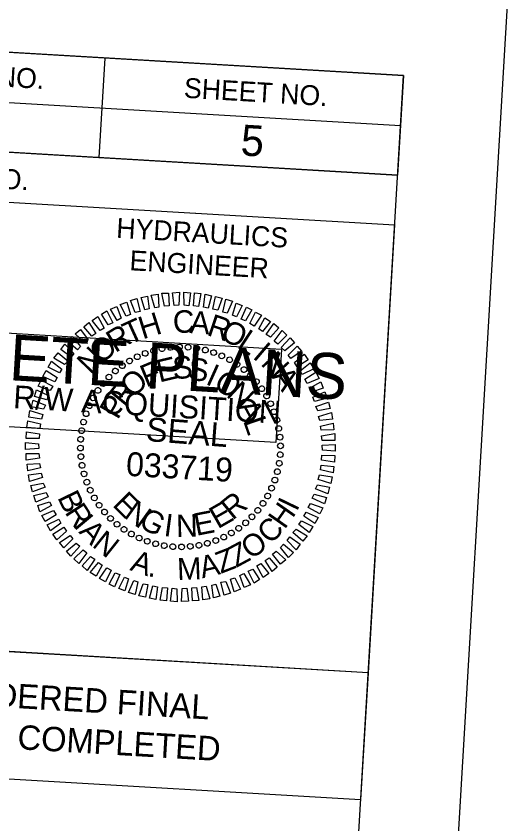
# Model space of a CAD drawing. Extents: x 2012250 to 2014096, y 444445 to 445643.
# Drawn here: x 2013972.6 to 2014096.1, y 445331.9 to 445534.5 of the extents above; entities that cross this region are included whole.
import ezdxf

# ---------------------------------------------------------------- set-up
doc = ezdxf.new("R2010")
doc.units = 0
for name, color, linetype in [('Old_Level_45', 7, 'Continuous'), ('Sheet Data Text CELL', 7, 'Continuous'), ('Sheet Plot Border Outside CELL', 7, 'Continuous'), ('Sheet Professional Seal CELL', 7, 'Continuous'), ('Sheet Profile Grid Minor CELL', 7, 'Continuous'), ('Sheet Sticker Exception Certification CELL', 7, 'Continuous'), ('Sheet Sticker Incomplete CELL', 7, 'Continuous')]:
    doc.layers.add(name, color=color, linetype=linetype)

msp = doc.modelspace()

# ---------------------------------------------------------------- linework, layer by layer
at = {"layer": 'Old_Level_45'}
for p, q in [((2013994.8, 445523.97), (2013993.33, 445499.01)), ((2013869.23, 445518.85), (2014068.93, 445507.08)), ((2013868.5, 445506.37), (2014068.2, 445494.6))]:
    msp.add_line(p, q, dxfattribs=at)
for points in [[(2014069.67, 445519.6), (2012572.27, 445607.87), (2012510.48, 444559.69), (2014007.88, 444471.42)], [(2013869.97, 445531.38), (2014069.67, 445519.6), (2014068.2, 445494.6), (2013868.5, 445506.37)], [(2013967.64, 445488), (2014067.46, 445482.12), (2014060.84, 445369.81), (2013961.02, 445375.7)]]:
    msp.add_lwpolyline(points, close=True, dxfattribs=at)
at = {"layer": 'Sheet Plot Border Outside CELL'}
msp.add_lwpolyline([(2012334.32, 444545.03), (2014031.37, 444445), (2014096.1, 445543.09), (2012399.05, 445643.13)], close=True, dxfattribs=at)
at = {"layer": 'Sheet Professional Seal CELL'}
for p, q in [((2014004.96, 445449.95), (2014004.96, 445449.95)), ((2014007.01, 445450.63), (2014007.01, 445450.63)), ((2014009.14, 445451.1), (2014009.14, 445451.1)), ((2014011.36, 445451.37), (2014011.36, 445451.37)), ((2014013.52, 445451.55), (2014013.52, 445451.55)), ((2014015.72, 445451.47), (2014015.72, 445451.47)), ((2014017.91, 445451.19), (2014017.91, 445451.19)), ((2014020.03, 445450.71), (2014020.03, 445450.71)), ((2014022.1, 445450.14), (2014022.1, 445450.14)), ((2014000.99, 445448.03), (2014000.99, 445448.03)), ((2014002.96, 445449.06), (2014002.96, 445449.06)), ((2014024.16, 445449.32), (2014024.16, 445449.32)), ((2014026.1, 445448.3), (2014026.1, 445448.3)), ((2013999.17, 445446.88), (2013999.17, 445446.88)), ((2014027.99, 445447.19), (2014027.99, 445447.19)), ((2014029.71, 445445.83), (2014029.71, 445445.83)), ((2013995.85, 445444.02), (2013995.85, 445444.02)), ((2013997.44, 445445.48), (2013997.44, 445445.48)), ((2014031.38, 445444.38), (2014031.38, 445444.38)), ((2013994.4, 445442.35), (2013994.4, 445442.35)), ((2014032.84, 445442.79), (2014032.84, 445442.79)), ((2013993.04, 445440.63), (2013993.04, 445440.63)), ((2014034.24, 445441.06), (2014034.24, 445441.06)), ((2013991.93, 445438.74), (2013991.93, 445438.74)), ((2014035.39, 445439.24), (2014035.39, 445439.24)), ((2013990.91, 445436.8), (2013990.91, 445436.8)), ((2014036.42, 445437.27), (2014036.42, 445437.27)), ((2013990.09, 445434.74), (2013990.09, 445434.74)), ((2014037.3, 445435.27), (2014037.3, 445435.27)), ((2013989.52, 445432.67), (2013989.52, 445432.67)), ((2014037.99, 445433.22), (2014037.99, 445433.22)), ((2013989.04, 445430.55), (2013989.04, 445430.55)), ((2014038.46, 445431.09), (2014038.46, 445431.09)), ((2013988.76, 445428.36), (2013988.76, 445428.36)), ((2014038.73, 445428.87), (2014038.73, 445428.87)), ((2013988.68, 445426.16), (2013988.68, 445426.16)), ((2014013.79, 445426.44), (2014013.79, 445426.44)), ((2014038.9, 445426.71), (2014038.9, 445426.71)), ((2013988.86, 445424), (2013988.86, 445424)), ((2014038.82, 445424.51), (2014038.82, 445424.51)), ((2013989.13, 445421.78), (2013989.13, 445421.78)), ((2014038.55, 445422.32), (2014038.55, 445422.32)), ((2013989.6, 445419.65), (2013989.6, 445419.65)), ((2014038.07, 445420.2), (2014038.07, 445420.2)), ((2013990.28, 445417.6), (2013990.28, 445417.6)), ((2014037.5, 445418.13), (2014037.5, 445418.13)), ((2013991.17, 445415.6), (2013991.17, 445415.6)), ((2014036.67, 445416.07), (2014036.67, 445416.07)), ((2013992.2, 445413.63), (2013992.2, 445413.63)), ((2014035.66, 445414.13), (2014035.66, 445414.13)), ((2013993.35, 445411.81), (2013993.35, 445411.81)), ((2014034.55, 445412.24), (2014034.55, 445412.24)), ((2013994.75, 445410.08), (2013994.75, 445410.08)), ((2014033.19, 445410.52), (2014033.19, 445410.52)), ((2013996.21, 445408.49), (2013996.21, 445408.49)), ((2014030.15, 445407.39), (2014030.15, 445407.39)), ((2014031.74, 445408.85), (2014031.74, 445408.85)), ((2013997.88, 445407.04), (2013997.88, 445407.04)), ((2013999.6, 445405.68), (2013999.6, 445405.68)), ((2014028.42, 445405.99), (2014028.42, 445405.99)), ((2014001.49, 445404.57), (2014001.49, 445404.57)), ((2014003.43, 445403.56), (2014003.43, 445403.56)), ((2014024.63, 445403.81), (2014024.63, 445403.81)), ((2014026.6, 445404.84), (2014026.6, 445404.84)), ((2014005.49, 445402.73), (2014005.49, 445402.73)), ((2014007.56, 445402.16), (2014007.56, 445402.16)), ((2014009.68, 445401.68), (2014009.68, 445401.68)), ((2014011.87, 445401.41), (2014011.87, 445401.41)), ((2014014.07, 445401.33), (2014014.07, 445401.33)), ((2014016.23, 445401.5), (2014016.23, 445401.5)), ((2014018.45, 445401.77), (2014018.45, 445401.77)), ((2014020.58, 445402.24), (2014020.58, 445402.24)), ((2014022.63, 445402.93), (2014022.63, 445402.93))]:
    msp.add_line(p, q, dxfattribs=at)
for points in [[(2014004.9, 445460.82), (2014003.93, 445463.88), (2014005.5, 445464.24), (2014005.97, 445461.11)], [(2014007.34, 445461.33), (2014006.47, 445464.53), (2014008.19, 445464.78), (2014008.4, 445461.51)], [(2014009.76, 445461.73), (2014009.15, 445464.98), (2014010.81, 445465.03), (2014010.97, 445461.81)], [(2014012.18, 445461.89), (2014011.82, 445465.12), (2014013.53, 445465.22), (2014013.38, 445461.97)], [(2014014.69, 445461.99), (2014014.63, 445465.25), (2014016.27, 445465.11), (2014015.88, 445461.87)], [(2014017.08, 445461.8), (2014017.27, 445465.05), (2014018.92, 445464.9), (2014018.28, 445461.68)], [(2014019.57, 445461.51), (2014019.96, 445464.74), (2014021.59, 445464.34), (2014020.75, 445461.24)], [(2014021.94, 445460.97), (2014022.58, 445464.13), (2014024.21, 445463.79), (2014023.13, 445460.75)], [(2014000.15, 445459.25), (2013998.72, 445462.13), (2014000.31, 445462.74), (2014001.28, 445459.63)], [(2014002.41, 445460.16), (2014001.28, 445463.14), (2014002.82, 445463.65), (2014003.67, 445460.39)], [(2014024.45, 445460.27), (2014025.14, 445463.48), (2014026.82, 445462.98), (2014025.49, 445459.96)], [(2014026.81, 445459.48), (2014027.74, 445462.53), (2014029.26, 445461.94), (2014027.84, 445459.07)], [(2013995.66, 445457.06), (2013993.97, 445459.71), (2013995.32, 445460.58), (2013996.8, 445457.59)], [(2013997.93, 445458.17), (2013996.25, 445460.98), (2013997.84, 445461.69), (2013998.92, 445458.72)], [(2014029, 445458.45), (2014030.34, 445461.52), (2014031.7, 445460.84), (2014030.13, 445458.03)], [(2014031.19, 445457.37), (2014032.62, 445460.24), (2014034.12, 445459.45), (2014032.26, 445456.75)], [(2013993.68, 445455.67), (2013991.67, 445458.19), (2013993.08, 445459.16), (2013994.67, 445456.26)], [(2014033.42, 445456.08), (2014034.94, 445458.85), (2014036.39, 445457.91), (2014034.34, 445455.43)], [(2013989.84, 445452.59), (2013987.42, 445454.79), (2013988.73, 445455.86), (2013990.69, 445453.34)], [(2013991.59, 445454.24), (2013989.53, 445456.57), (2013990.79, 445457.69), (2013992.58, 445454.88)], [(2014035.29, 445454.62), (2014037.21, 445457.41), (2014038.44, 445456.29), (2014036.35, 445453.96)], [(2013987.98, 445450.8), (2013985.5, 445452.9), (2013986.68, 445454.13), (2013988.74, 445451.65)], [(2014037.25, 445453), (2014039.26, 445455.64), (2014040.49, 445454.46), (2014038.16, 445452.25)], [(2014039.05, 445451.34), (2014041.25, 445453.82), (2014042.38, 445452.55), (2014039.96, 445450.54)], [(2013986.37, 445448.99), (2013983.78, 445450.84), (2013984.81, 445452.24), (2013987.08, 445449.9)], [(2013984.76, 445447.08), (2013982.05, 445448.74), (2013983.13, 445450.08), (2013985.61, 445447.93)], [(2014040.75, 445449.49), (2014043.03, 445451.71), (2014044.16, 445450.44), (2014041.45, 445448.65)], [(2013983.43, 445445), (2013980.66, 445446.42), (2013981.5, 445447.92), (2013984.09, 445445.92)], [(2014042.39, 445447.59), (2014044.82, 445449.7), (2014045.79, 445448.29), (2014043.03, 445446.55)], [(2014043.77, 445445.55), (2014046.34, 445447.51), (2014047.2, 445446), (2014044.31, 445444.57)], [(2013982.3, 445442.77), (2013979.27, 445444.1), (2013980.11, 445445.6), (2013982.86, 445443.84)], [(2014044.95, 445443.43), (2014047.71, 445445.17), (2014048.57, 445443.62), (2014045.59, 445442.39)], [(2013981.17, 445440.63), (2013978.13, 445441.71), (2013978.87, 445443.22), (2013981.78, 445441.65)], [(2014046.12, 445441.16), (2014049.01, 445442.74), (2014049.57, 445441.16), (2014046.66, 445440.18)], [(2013980.28, 445438.28), (2013977.23, 445439.11), (2013977.67, 445440.74), (2013980.74, 445439.3)], [(2014046.99, 445438.95), (2014050.02, 445440.28), (2014050.58, 445438.64), (2014047.42, 445437.83)], [(2013979.49, 445435.92), (2013976.42, 445436.5), (2013976.87, 445438.18), (2013979.95, 445436.95)], [(2014047.75, 445436.55), (2014050.87, 445437.67), (2014051.33, 445436.09), (2014048.19, 445435.48)], [(2013978.94, 445433.4), (2013975.77, 445433.89), (2013976.07, 445435.57), (2013979.26, 445434.58)], [(2014048.41, 445434.11), (2014051.67, 445435.07), (2014051.87, 445433.41), (2014048.69, 445433.04)], [(2013978.55, 445431.02), (2013975.31, 445431.31), (2013975.51, 445432.95), (2013978.72, 445432.21)], [(2014048.86, 445431.68), (2014052.06, 445432.44), (2014052.26, 445430.73), (2014049.1, 445430.62)], [(2013978.36, 445428.52), (2013975.1, 445428.57), (2013975.2, 445430.26), (2013978.43, 445429.72)], [(2014049.17, 445429.26), (2014052.46, 445429.77), (2014052.51, 445428.06), (2014049.3, 445428.05)], [(2013978.26, 445426.03), (2013974.99, 445425.82), (2013974.99, 445427.52), (2013978.23, 445427.23)], [(2014049.33, 445426.85), (2014052.6, 445427.05), (2014052.6, 445425.35), (2014049.36, 445425.64)], [(2013978.42, 445423.61), (2013975.13, 445423.1), (2013975.08, 445424.81), (2013978.29, 445424.82)], [(2014049.23, 445424.35), (2014052.49, 445424.3), (2014052.39, 445422.61), (2014049.16, 445423.15)], [(2013978.72, 445421.19), (2013975.52, 445420.43), (2013975.33, 445422.14), (2013978.49, 445422.26)], [(2014049.04, 445421.85), (2014052.27, 445421.56), (2014052.08, 445419.92), (2014048.87, 445420.66)], [(2013979.18, 445418.76), (2013975.92, 445417.8), (2013975.72, 445419.46), (2013978.9, 445419.83)], [(2014048.65, 445419.47), (2014051.82, 445418.98), (2014051.52, 445417.3), (2014048.32, 445418.29)], [(2013979.84, 445416.32), (2013976.72, 445415.2), (2013976.26, 445416.78), (2013979.4, 445417.39)], [(2014048.1, 445416.95), (2014051.17, 445416.37), (2014050.72, 445414.69), (2014047.63, 445415.93)], [(2013980.6, 445413.92), (2013977.57, 445412.59), (2013977.01, 445414.23), (2013980.17, 445415.04)], [(2014047.31, 445414.59), (2014050.36, 445413.76), (2014049.92, 445412.14), (2014046.84, 445413.57)], [(2013981.47, 445411.71), (2013978.57, 445410.13), (2013978.02, 445411.72), (2013980.93, 445412.7)], [(2014046.42, 445412.24), (2014049.46, 445411.16), (2014048.72, 445409.65), (2014045.8, 445411.23)], [(2013982.64, 445409.44), (2013979.88, 445407.7), (2013979.02, 445409.25), (2013982, 445410.48)], [(2014045.29, 445410.1), (2014048.31, 445408.77), (2014047.48, 445407.27), (2014044.72, 445409.04)], [(2013983.82, 445407.32), (2013981.25, 445405.36), (2013980.39, 445406.87), (2013983.27, 445408.3)], [(2014044.15, 445407.87), (2014046.93, 445406.45), (2014046.09, 445404.95), (2014043.5, 445406.95)], [(2013985.2, 445405.28), (2013982.77, 445403.17), (2013981.8, 445404.58), (2013984.56, 445406.32)], [(2014042.83, 445405.79), (2014045.54, 445404.13), (2014044.46, 445402.79), (2014041.98, 445404.94)], [(2013986.84, 445403.38), (2013984.56, 445401.16), (2013983.43, 445402.43), (2013986.14, 445404.22)], [(2014041.21, 445403.88), (2014043.81, 445402.03), (2014042.78, 445400.64), (2014040.51, 445402.97)], [(2013988.53, 445401.53), (2013986.34, 445399.05), (2013985.21, 445400.32), (2013987.63, 445402.33)], [(2014039.61, 445402.07), (2014042.09, 445399.97), (2014040.91, 445398.74), (2014038.85, 445401.22)], [(2013990.34, 445399.87), (2013988.33, 445397.23), (2013987.1, 445398.41), (2013989.43, 445400.62)], [(2014037.75, 445400.28), (2014040.17, 445398.08), (2014038.86, 445397.01), (2014036.9, 445399.53)], [(2013992.3, 445398.25), (2013990.38, 445395.46), (2013989.15, 445396.58), (2013991.24, 445398.92)], [(2013994.17, 445396.79), (2013992.65, 445394.02), (2013991.2, 445394.96), (2013993.25, 445397.44)], [(2014033.91, 445397.2), (2014035.91, 445394.68), (2014034.5, 445393.71), (2014032.92, 445396.61)], [(2014036, 445398.63), (2014038.06, 445396.31), (2014036.79, 445395.18), (2014035.01, 445397.99)], [(2013996.39, 445395.51), (2013994.97, 445392.63), (2013993.47, 445393.42), (2013995.33, 445396.12)], [(2014031.92, 445395.82), (2014033.62, 445393.16), (2014032.27, 445392.29), (2014030.79, 445395.28)], [(2013998.58, 445394.43), (2013997.25, 445391.35), (2013995.89, 445392.03), (2013997.46, 445394.84)], [(2014000.78, 445393.39), (2013999.85, 445390.34), (2013998.33, 445390.93), (2013999.75, 445393.81)], [(2014027.44, 445393.63), (2014028.87, 445390.74), (2014027.28, 445390.13), (2014026.31, 445393.24)], [(2014029.65, 445394.7), (2014031.34, 445391.89), (2014029.75, 445391.19), (2014028.67, 445394.15)], [(2014003.14, 445392.6), (2014002.44, 445389.39), (2014000.77, 445389.89), (2014002.1, 445392.92)], [(2014005.65, 445391.91), (2014005.01, 445388.74), (2014003.38, 445389.08), (2014004.46, 445392.13)], [(2014008.02, 445391.36), (2014007.63, 445388.13), (2014006, 445388.53), (2014006.83, 445391.63)], [(2014010.51, 445391.07), (2014010.32, 445387.82), (2014008.67, 445387.97), (2014009.31, 445391.19)], [(2014017.82, 445391.14), (2014018.43, 445387.9), (2014016.78, 445387.84), (2014016.62, 445391.06)], [(2014020.25, 445391.55), (2014021.12, 445388.34), (2014019.4, 445388.09), (2014019.19, 445391.36)], [(2014022.69, 445392.05), (2014023.66, 445388.99), (2014022.08, 445388.63), (2014021.62, 445391.77)], [(2014025.18, 445392.71), (2014026.31, 445389.74), (2014024.77, 445389.22), (2014023.91, 445392.48)], [(2014012.9, 445390.88), (2014012.96, 445387.62), (2014011.31, 445387.76), (2014011.71, 445391)], [(2014015.41, 445390.98), (2014015.77, 445387.75), (2014014.06, 445387.65), (2014014.2, 445390.9)]]:
    msp.add_lwpolyline(points, close=True, dxfattribs=at)
for centre, major_axis in [((2014009.17, 445451.09), (-0.133, 0.708)), ((2014011.34, 445451.39), (-0.071, 0.717)), ((2014013.52, 445451.51), (-0.008, 0.72)), ((2014015.71, 445451.44), (0.055, 0.718)), ((2014017.88, 445451.18), (0.117, 0.71)), ((2014002.95, 445449.05), (-0.311, 0.649)), ((2014004.96, 445449.91), (-0.254, 0.674)), ((2014007.04, 445450.59), (-0.194, 0.693)), ((2014020.02, 445450.73), (0.179, 0.697)), ((2014022.11, 445450.1), (0.239, 0.679)), ((2014024.14, 445449.28), (0.297, 0.656)), ((2014001.02, 445448.02), (-0.367, 0.62)), ((2014026.1, 445448.29), (0.353, 0.627)), ((2014027.95, 445447.14), (0.407, 0.594)), ((2013997.46, 445445.47), (-0.469, 0.546)), ((2013999.19, 445446.82), (-0.419, 0.585)), ((2014029.7, 445445.82), (0.457, 0.557)), ((2013995.87, 445443.97), (-0.515, 0.504)), ((2014031.33, 445444.36), (0.504, 0.515)), ((2013994.41, 445442.35), (-0.557, 0.457)), ((2014032.83, 445442.77), (0.546, 0.469)), ((2014034.18, 445441.04), (0.585, 0.419)), ((2013993.09, 445440.6), (-0.594, 0.407)), ((2014035.38, 445439.21), (0.62, 0.367)), ((2013990.95, 445436.79), (-0.656, 0.297)), ((2013991.94, 445438.74), (-0.627, 0.353)), ((2014036.41, 445437.28), (0.649, 0.311)), ((2014037.27, 445435.27), (0.674, 0.254)), ((2013990.13, 445434.76), (-0.679, 0.239)), ((2014037.95, 445433.19), (0.693, 0.194)), ((2013989.5, 445432.66), (-0.697, 0.179)), ((2014038.44, 445431.06), (0.708, 0.133)), ((2013989.05, 445430.52), (-0.71, 0.117)), ((2014038.75, 445428.89), (0.717, 0.071)), ((2013988.79, 445428.35), (-0.718, 0.055)), ((2013988.72, 445426.16), (-0.72, -0.008)), ((2014038.87, 445426.71), (0.72, 0.008)), ((2013988.84, 445423.98), (-0.717, -0.071)), ((2014038.8, 445424.52), (0.718, -0.055)), ((2013989.14, 445421.81), (-0.708, -0.133)), ((2014038.54, 445422.35), (0.71, -0.117)), ((2013989.64, 445419.68), (-0.693, -0.194)), ((2014038.09, 445420.21), (0.697, -0.179)), ((2013990.32, 445417.6), (-0.674, -0.254)), ((2014037.45, 445418.12), (0.679, -0.239)), ((2013991.18, 445415.59), (-0.649, -0.311)), ((2014036.64, 445416.09), (0.656, -0.297)), ((2013992.21, 445413.66), (-0.62, -0.367)), ((2014035.65, 445414.13), (0.627, -0.353)), ((2013993.41, 445411.83), (-0.585, -0.419)), ((2014033.18, 445410.53), (0.557, -0.457)), ((2014034.49, 445412.28), (0.594, -0.407)), ((2013994.76, 445410.11), (-0.546, -0.469)), ((2013996.26, 445408.51), (-0.504, -0.515)), ((2014031.72, 445408.9), (0.515, -0.504)), ((2013997.88, 445407.05), (-0.457, -0.557)), ((2014030.12, 445407.4), (0.469, -0.546)), ((2013999.63, 445405.74), (-0.407, -0.594)), ((2014001.49, 445404.58), (-0.353, -0.627)), ((2014026.57, 445404.85), (0.367, -0.62)), ((2014028.4, 445406.05), (0.419, -0.585)), ((2014003.44, 445403.59), (-0.297, -0.656)), ((2014005.47, 445402.78), (-0.239, -0.679)), ((2014022.63, 445402.96), (0.254, -0.674)), ((2014024.64, 445403.82), (0.311, -0.649)), ((2014007.57, 445402.14), (-0.179, -0.697)), ((2014009.71, 445401.69), (-0.117, -0.71)), ((2014011.88, 445401.43), (-0.055, -0.718)), ((2014014.07, 445401.36), (0.008, -0.72)), ((2014016.25, 445401.48), (0.071, -0.717)), ((2014018.42, 445401.79), (0.133, -0.708)), ((2014020.55, 445402.28), (0.194, -0.693))]:
    msp.add_ellipse(centre, major_axis=major_axis, ratio=0.999708, dxfattribs=at)
at = {"layer": 'Sheet Sticker Exception Certification CELL'}
for p, q in [((2013861.14, 445381.6), (2014060.84, 445369.83)), ((2014060.84, 445369.81), (2014058.96, 445337.89)), ((2014058.96, 445337.91), (2013859.26, 445349.68))]:
    msp.add_line(p, q, dxfattribs=at)
at = {"layer": 'Sheet Sticker Incomplete CELL'}
msp.add_lwpolyline([(2013890.95, 445436.18), (2013892.34, 445459.64), (2014039.08, 445450.99), (2014037.7, 445427.53)], close=True, dxfattribs=at)

# ---------------------------------------------------------------- texts
at = {"layer": 'Old_Level_45'}
for s, height, p in [('PROJECT REFERENCE NO.', 5.0001, (2013891.62, 445521.39)), ('SHEET NO.', 5, (2014014.55, 445514.04)), ('R/W SHEET NO.', 5.0001, (2013924.86, 445493.83)), ('HYDRAULICS', 5, (2013997.6, 445478.93)), ('ENGINEER', 5, (2014000.93, 445470.77))]:
    msp.add_text(s, height=height, rotation=356.6264, dxfattribs=at).set_placement(p)
at = {"layer": 'Sheet Data Text CELL'}
msp.add_text('5', height=7.75, rotation=356.6264, dxfattribs=at).set_placement((2014028.76, 445499.58))
at = {"layer": 'Sheet Professional Seal CELL'}
for s, height, rotation, p in [('H', 5.64, 17.2459, (2014004.31, 445453.39)), ('C', 5.64, 2.8463, (2014012.02, 445454.94)), ('A', 5.64, 355.6467, (2014015.98, 445455.01)), ('T', 5.64, 24.4462, (2014000.97, 445451.93)), ('R', 5.64, 341.2475, (2014020.16, 445454.56)), ('O', 5.64, 334.0476, (2014023.46, 445453.61)), ('R', 5.64, 31.6469, (2013997.45, 445449.94)), ('L', 5.64, 326.8473, (2014027.74, 445451.51)), ('O', 5.64, 38.8482, (2013993.82, 445447.05)), ('I', 5.64, 319.6466, (2014031.65, 445448.87)), ('N', 5.64, 46.0499, (2013991.36, 445444.29)), ('N', 5.64, 312.4453, (2014033.7, 445447.2)), ('F', 5.64, 22.5935, (2014005.2, 445441.27)), ('E', 5.64, 13.2375, (2014008.49, 445442.58)), ('S', 5.64, 3.882, (2014011.99, 445443.42)), ('S', 5.64, 354.5268, (2014015.59, 445443.26)), ('I', 5.64, 335.816, (2014019.84, 445442.31)), ('O', 5.64, 41.3077, (2014001.73, 445438.52)), ('O', 5.64, 326.4599, (2014021.79, 445441.49)), ('A', 5.64, 305.2436, (2014036.47, 445444.08)), ('R', 5.64, 50.6661, (2013999.84, 445436.17)), ('N', 5.64, 317.103, (2014025.02, 445439.3)), ('P', 5.64, 60.0253, (2013998.06, 445433.07)), ('A', 5.64, 298.3867, (2014027.71, 445436.53)), ('SEAL', 5.998, 355.6264, (2014005.02, 445427.95)), ('L', 5.64, 289.0273, (2014029.46, 445432.98)), ('E', 5.64, 314.9033, (2013996.5, 445411.78)), ('R', 5.64, 39.1078, (2014026.83, 445407.89)), ('N', 5.64, 324.2604, (2013999.34, 445408.91)), ('E', 5.64, 29.7505, (2014023.14, 445405.75)), ('G', 5.64, 333.6167, (2014003, 445406.44)), ('I', 5.64, 352.3276, (2014009.43, 445404.15)), ('N', 5.64, 1.6828, (2014012.76, 445403.81)), ('E', 5.64, 11.0382, (2014017.74, 445404.11))]:
    msp.add_text(s, height=height, rotation=rotation, dxfattribs=at).set_placement(p)
at = {"layer": 'Sheet Profile Grid Minor CELL'}
for s, height, rotation, p in [('033719', 5.998, 356.6264, (2014000.03, 445419.22)), ('B', 5.5, 295.7793, (2013982.85, 445413.79)), ('I', 5.5, 64.2191, (2014042.93, 445410.06)), ('R', 5.5, 302.9061, (2013984.66, 445410.05)), ('H', 5.5, 54.9743, (2014039.92, 445405.59)), ('I', 5.5, 309.8326, (2013986.84, 445406.66)), ('A', 5.5, 313.353, (2013988.11, 445405.04)), ('C', 5.5, 46.1015, (2014036.4, 445401.81)), ('N', 5.5, 321.5388, (2013991.42, 445401.6)), ('O', 5.5, 35.397, (2014031.43, 445398.04)), ('Z', 5.5, 21.1435, (2014023.89, 445394.57)), ('Z', 5.5, 28.2703, (2014027.77, 445396.07)), ('A', 5.5, 340.9157, (2014000.92, 445395.58)), ('A', 5.5, 12.9577, (2014019.25, 445393.46)), ('M', 5.5, 2.2818, (2014013.05, 445393.02)), ('.', 5.5, 349.1015, (2014005.45, 445394.07))]:
    msp.add_text(s, height=height, rotation=rotation, dxfattribs=at).set_placement(p)
at = {"layer": 'Sheet Sticker Exception Certification CELL'}
for s, p in [('DOCUMENT NOT CONSIDERED FINAL', (2013871.92, 445366.87)), ('UNLESS ALL SIGNATURES COMPLETED', (2013865.59, 445356.96))]:
    msp.add_text(s, height=6.124, rotation=356.6264, dxfattribs=at).set_placement(p)
at = {"layer": 'Sheet Sticker Incomplete CELL'}
for s, height, p in [('INCOMPLETE PLANS', 11.52, (2013900.58, 445447.33)), ('DO NOT USE FOR R/W ACQUISITION', 5.76, (2013903.41, 445440.2))]:
    msp.add_text(s, height=height, rotation=356.6264, dxfattribs=at).set_placement(p)

doc.saveas('drawing.dxf')
